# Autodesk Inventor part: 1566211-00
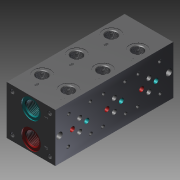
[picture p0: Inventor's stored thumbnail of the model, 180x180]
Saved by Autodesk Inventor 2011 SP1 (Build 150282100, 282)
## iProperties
Created: 2015-09
Part Number: 1566211-00
Catalog Web Link: www.cadenas.de
Description: P2A*L-Manifolds for ISO 4401-03 (CETOP 03) valves with side ports
Vendor: DUPLOMATIC
Document SubType Name: Modeling
Designer: PARTuser1
Manufacturer: DUPLOMATIC
Mass: 724.364 g
Surface Area: 890.578 cm^2
Volume: 724.364 cm^3
Density: 1 g/cm^3
Category: PARTsolutions
Company: DUPLOMATIC
Title: P2A3L/11
Author: Cadenas PARTsolutions
Comments: Manifolds for ISO 4401-03 (CETOP 03) valves with side ports
PSOL_IDENT_0: {$CADENAS_DATA\23d-libs\duplomatic\05_subplates_and_manifolds\52100\p2al.prj},162 {VTYP=3D},{NB=1566
PSOL_IDENT_1: 211-00},{LINA=P2A3L/11},{NN=P2A*L},{DATE=23.07.2015 05:38:35},{GEOMDATE=08.11.2012 00:00:00},{VERSIO
PSOL_IDENT_2: N=},{LINEID=10},{LINESUBID=-1},{WBVAR=VER}  {NB=1566211-00},{LINA=P2A3L/11},{KT=DUMMY},{CODE=1566211
PSOL_IDENT_3: -00},{TIPO=P2A},{VER=3},{PORT=L = Side ports},{SER=11}
NN: P2A*L
NT: Manifolds for ISO 4401-03 (CETOP 03) valves with side ports
NB: 1566211-00
NBSYN: $CODE.
LINA: P2A3L/11
OFFICIAL_STANDARD_NUMBERS: NO
TIPO: P2A
VER: 3 = 3 mounting positions
PORT: L = Side ports
SER: 11
SUPPLIER: DUPLOMATIC
ARTICLENO: 1566211-00
BOMINFO: P2A3L/11
CREATOR: CADENAS GmbH
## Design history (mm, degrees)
sketch "Sketch_1"
  geometry: L1 (-35, 170)-(-35, 0); L2 (-35, 0)-(35, 0); L3 (35, 0)-(35, 170); L4 (35, 170)-(-35, 170)
  constraints: 8 end point
extrude "Extrusion1" join sketch "Sketch_1" stored distance "d0" = 70; taper "d1" = 0 deg
sketch "Sketch_2"
  geometry: L1 (35, 6)-(-35, 6); L2 (-35, 6)-(-35, 10); L3 (-35, 10)-(-34.324, 9.323); L4 (-34.324, 9.323)-(-16.919, 9.323); L5 (-16.919, 9.323)-(-16.588, 8.75); L6 (-16.588, 8.75)-(25, 8.75); L7 (25, 8.75)-(25, 10.5); L8 (25, 10.5)-(35, 10.5); L9 (35, 10.5)-(35, 6); L10 (35, 6)-(-35, 6)
  constraints: 20 end point
revolve "Revolution1" sketch "Sketch_2" stored, may be unused: angle "d2" = 360 deg
thread "Thread1" dims "d3" = 12.3235, "d4" = 0
sketch "Sketch_3"
  geometry: L1 (35, 164)-(-35, 164); L2 (-35, 164)-(-35, 168); L3 (-35, 168)-(-34.324, 167.323); L4 (-34.324, 167.323)-(-16.919, 167.323); L5 (-16.919, 167.323)-(-16.588, 166.75); L6 (-16.588, 166.75)-(25, 166.75); L7 (25, 166.75)-(25, 168.5); L8 (25, 168.5)-(35, 168.5); L9 (35, 168.5)-(35, 164); L10 (35, 164)-(-35, 164)
  constraints: 20 end point
revolve "Revolution2" sketch "Sketch_3" stored, may be unused: angle "d5" = 360 deg
thread "Thread2" dims "d6" = 12.3235, "d7" = 0
sketch "Sketch4"
  geometry: 1 further point
hole "Hole1" sketch "Sketch4" at (14.75, 19.5) diameter "d8" = 4.134; stored, may be unused: countersink angle "d12" = 90 deg, drill point angle "d14" = 120 deg; dims "d9" = 9, "d10" = 5, "d11" = 2, "d13" = 10.80662
pattern_linear "Rectangular Pattern1" dims "d17" = 50, "d20" = 40.50694
sketch "Sketch5"
  geometry: 1 further point
hole "Hole2" sketch "Sketch5" at (14.75, 50.5) diameter "d21" = 4.134; stored, may be unused: countersink angle "d25" = 90 deg, drill point angle "d27" = 120 deg; dims "d22" = 9, "d23" = 5, "d24" = 2, "d26" = 10.80662
pattern_linear "Rectangular Pattern2" dims "d30" = 40.50694
sketch "Sketch6"
  geometry: 1 further point
hole "Hole3" sketch "Sketch6" at (36.25, 24.6) diameter "d34" = 7; stored, may be unused: countersink angle "d38" = 90 deg, drill point angle "d40" = 120 deg; dims "d35" = 6, "d36" = 4, "d37" = 2, "d39" = 15.97927
pattern_linear "Rectangular Pattern3" dims "d43" = 50, "d46" = 0
sketch "Sketch7"
  geometry: 1 further point
hole "Hole4" sketch "Sketch7" at (36.25, 45.4) diameter "d47" = 7; stored, may be unused: countersink angle "d51" = 90 deg, drill point angle "d53" = 120 deg; dims "d48" = 6, "d49" = 4, "d50" = 2, "d52" = 15.97927
pattern_linear "Rectangular Pattern4" dims "d56" = 50, "d59" = 0
sketch "Sketch8"
  geometry: 1 further point
hole "Hole5" sketch "Sketch8" at (27.45, 35) diameter "d60" = 7; stored, may be unused: countersink angle "d64" = 90 deg, drill point angle "d66" = 120 deg; dims "d61" = 6, "d62" = 4, "d63" = 2, "d65" = 15.97927
pattern_linear "Rectangular Pattern5" dims "d69" = 50, "d72" = 0
sketch "Sketch9"
  geometry: 1 further point
hole "Hole6" sketch "Sketch9" at (44.95, 35) diameter "d73" = 7; stored, may be unused: countersink angle "d77" = 90 deg, drill point angle "d79" = 120 deg; dims "d74" = 6, "d75" = 4, "d76" = 2, "d78" = 15.97927
pattern_linear "Rectangular Pattern6" dims "d82" = 50, "d85" = 0
sketch "Sketch_14"
  geometry: L1 (-19, -35)-(-19, -11.684); L2 (-19, -11.684)-(-11.525, -16); L3 (-11.525, -16)-(-11.525, -33.644); L4 (-11.525, -33.644)-(-10.669, -34.5); L5 (-10.669, -34.5)-(-7, -34.5); L6 (-7, -34.5)-(-7, -35); L7 (-7, -35)-(-19, -35); L8 (-19, -35)-(-19, -11.684)
  constraints: 16 end point
revolve "Revolution3" sketch "Sketch_14" stored, may be unused: angle "d86" = 360 deg
thread "Thread3" dims "d87" = 12.144, "d88" = 0
pattern_linear "Rectangular Pattern7" dims "d91" = 38
sketch "Sketch11"
  geometry: 1 further point
hole "Hole7" sketch "Sketch11" at (8, -8) diameter "d95" = 4.917; stored, may be unused: countersink angle "d99" = 90 deg, drill point angle "d101" = 120 deg; dims "d96" = 12, "d97" = 6, "d98" = 2, "d100" = 16.58058
pattern_linear "Rectangular Pattern8" dims "d104" = 54, "d107" = 54
sketch "Sketch_18"
  geometry: L1 (0, 19)-(85, 19); L2 (85, 19)-(85, 11.5); L3 (85, 11.5)-(24.448, 11.5); L4 (24.448, 11.5)-(23.4, 9.684); L5 (23.4, 9.684)-(2.562, 9.684); L6 (2.562, 9.684)-(1.4, 8.523); L7 (1.4, 8.523)-(1.4, 5); L8 (1.4, 5)-(0, 5); L9 (0, 5)-(0, 19); L10 (0, 19)-(85, 19)
  constraints: 20 end point
revolve "Revolution4" sketch "Sketch_18" stored, may be unused: angle "d108" = 360 deg
thread "Thread4" dims "d109" = 14.838, "d110" = 0
sketch "Sketch_19"
  geometry: L1 (0, -19)-(85, -19); L2 (85, -19)-(85, -26.5); L3 (85, -26.5)-(24.448, -26.5); L4 (24.448, -26.5)-(23.4, -28.316); L5 (23.4, -28.316)-(2.562, -28.316); L6 (2.562, -28.316)-(1.4, -29.477); L7 (1.4, -29.477)-(1.4, -33); L8 (1.4, -33)-(0, -33); L9 (0, -33)-(0, -19); L10 (0, -19)-(85, -19)
  constraints: 20 end point
revolve "Revolution5" sketch "Sketch_19" stored, may be unused: angle "d111" = 360 deg
thread "Thread5" dims "d112" = 14.838, "d113" = 0
sketch "Sketch_20"
  geometry: L1 (85, 19)-(170, 19); L2 (170, 19)-(170, 4); L3 (170, 4)-(169.5, 4); L4 (169.5, 4)-(169.5, 8.523); L5 (169.5, 8.523)-(168.338, 9.684); L6 (168.338, 9.684)-(147.5, 9.684); L7 (147.5, 9.684)-(146.452, 11.5); L8 (146.452, 11.5)-(85, 11.5); L9 (85, 11.5)-(85, 19); L10 (85, 19)-(170, 19)
  constraints: 20 end point
revolve "Revolution6" sketch "Sketch_20" stored, may be unused: angle "d114" = 360 deg
thread "Thread6" dims "d115" = 14.838, "d116" = 0
sketch "Sketch_21"
  geometry: L1 (85, -19)-(170, -19); L2 (170, -19)-(170, -34); L3 (170, -34)-(169.5, -34); L4 (169.5, -34)-(169.5, -29.477); L5 (169.5, -29.477)-(168.338, -28.316); L6 (168.338, -28.316)-(147.5, -28.316); L7 (147.5, -28.316)-(146.452, -26.5); L8 (146.452, -26.5)-(85, -26.5); L9 (85, -26.5)-(85, -19); L10 (85, -19)-(170, -19)
  constraints: 20 end point
revolve "Revolution7" sketch "Sketch_21" stored, may be unused: angle "d117" = 360 deg
thread "Thread7" dims "d118" = 14.838, "d119" = 0
sketch "Sketch_22"
  geometry: L1 (-35, 47)-(-35, 25); L2 (-35, 25)-(35, 25); L3 (35, 25)-(35, 47); L4 (35, 47)-(-35, 47)
  constraints: 8 end point
extrude "Extrusion2" cut sketch "Sketch_22" distance "d120" = 0.5; taper "d121" = 0 deg
sketch "Sketch_23"
  geometry: L1 (-35, 47)-(-35, 25); L2 (-35, 25)-(35, 25); L3 (35, 25)-(35, 47); L4 (35, 47)-(-35, 47)
  constraints: 8 end point
extrude "Extrusion3" join sketch "Sketch_23" distance "d122" = 0.5; taper "d123" = 0 deg
sketch "Sketch_24"
  geometry: L1 (-16.745, 30.5)-(13.079, 30.5); L2 (13.079, 39.5)-(-16.745, 39.5); L3 (8.002, 35.622)-(9.027, 35.622); L4 (9.027, 35.622)-(9.027, 37.486); L5 (9.027, 37.486)-(8.569, 37.486); L6 (8.569, 37.486)-(8.569, 35.997); L7 (8.569, 35.997)-(7.979, 35.997); L8 (7.994, 37.751)-(9.027, 37.752); L9 (9.027, 37.752)-(9.027, 38.127); L10 (9.027, 38.127)-(8.021, 38.127); L11 (4.708, 31.873)-(5.302, 31.873); L12 (6.361, 32.917)-(6.361, 34.378); L13 (6.361, 34.378)-(5.903, 34.378); L14 (5.903, 34.378)-(5.903, 32.943); L15 (5.234, 32.249)-(4.708, 32.249); L16 (4.708, 32.249)-(4.708, 31.873); L17 (6.41, 36.628)-(6.41, 38.127); L18 (6.41, 38.127)-(5.951, 38.127); L19 (5.951, 38.127)-(5.951, 36.632); L20 (5.951, 36.632)-(5.945, 36.459); L21 (4.716, 36.47)-(4.712, 36.651); L22 (4.712, 36.651)-(4.712, 38.127); L23 (4.712, 38.127)-(4.254, 38.127); L24 (4.254, 38.127)-(4.254, 36.662); L25 (2.579, 31.873)-(3.345, 31.873); L26 (3.371, 34.378)-(2.579, 34.378); L27 (2.579, 34.378)-(2.579, 34.003); L28 (2.579, 34.003)-(3.292, 34.003); L29 (4.036, 33.315)-(2.579, 33.315); L30 (2.579, 33.315)-(2.579, 32.94); L31 (2.579, 32.94)-(4.036, 32.94); L32 (3.292, 32.249)-(2.579, 32.249); L33 (2.579, 32.249)-(2.579, 31.873); L34 (2.567, 36.516)-(3.3, 36.516); L35 (3.3, 36.516)-(3.3, 35.622); L36 (3.3, 35.622)-(3.758, 35.622); L37 (3.758, 35.622)-(3.758, 37.486); L38 (3.758, 37.486)-(3.3, 37.486); L39 (3.3, 37.486)-(3.3, 36.891); L40 (3.3, 36.891)-(2.612, 36.891); L41 (2.616, 37.751)-(3.758, 37.752); L42 (3.758, 37.752)-(3.758, 38.127); L43 (3.758, 38.127)-(2.59, 38.127); L44 (-0.321, 35.622)-(0.272, 35.622); L45 (1.332, 36.666)-(1.332, 38.127); L46 (1.332, 38.127)-(0.873, 38.127); L47 (0.873, 38.127)-(0.873, 36.692); L48 (0.206, 35.997)-(-0.321, 35.997); L49 (-0.321, 35.997)-(-0.321, 35.622); L50 (-1.575, 31.873)-(-0.55, 31.873); L51 (-0.55, 31.873)-(-0.55, 33.734); L52 (-0.55, 33.734)-(-1.008, 33.734); L53 (-1.008, 33.734)-(-1.008, 32.249); L54 (-1.008, 32.249)-(-1.598, 32.249); L55 (-1.583, 34.003)-(-0.55, 34.003); L56 (-0.55, 34.003)-(-0.55, 34.378); L57 (-0.55, 34.378)-(-1.557, 34.378); L58 (-3.656, 31.873)-(-3.198, 31.873); L59 (-3.198, 31.873)-(-3.198, 33.734); L60 (-3.198, 33.734)-(-3.656, 33.734); L61 (-3.656, 33.734)-(-3.656, 31.873); L62 (-3.656, 33.998)-(-3.198, 33.998); L63 (-3.198, 33.998)-(-3.198, 34.378); L64 (-3.198, 34.378)-(-3.656, 34.378)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; A1 r 4.5 centre (-16.745, 35) between (-16.745, 39.5) and (-16.745, 30.5); A2 r 5.4 centre (16.064, 35) between (13.079, 39.5) and (13.079, 30.5); A3 r 1.744 centre (8.513, 36.864) between (6.77, 36.921) and (6.989, 36.018); A4 r 0.637 centre (7.554, 36.312) between (6.989, 36.018) and (7.198, 35.783); A5 r 0.992 centre (7.726, 36.623) between (7.198, 35.783) and (7.641, 35.635); A6 r 4.787 centre (7.991, 40.409) between (7.641, 35.635) and (8.002, 35.622); A7 r 1.499 centre (8.013, 37.496) between (7.725, 36.025) and (7.979, 35.997); A8 r 0.575 centre (7.871, 36.581) between (7.427, 36.215) and (7.725, 36.025); A9 r 1.675 centre (8.945, 36.923) between (7.27, 36.903) and (7.427, 36.215); A10 r 1.373 centre (8.643, 36.858) between (7.476, 37.582) and (7.27, 36.903); A11 r 0.629 centre (7.901, 37.119) between (7.814, 37.741) and (7.476, 37.582); A12 r 1.546 centre (7.989, 36.206) between (7.994, 37.751) and (7.814, 37.741); A13 r 5.147 centre (8.198, 32.983) between (8.021, 38.127) and (7.513, 38.084); A14 r 0.682 centre (7.595, 37.408) between (7.513, 38.084) and (7.052, 37.819); A15 r 1.728 centre (8.497, 36.873) between (7.052, 37.819) and (6.77, 36.921); A16 r 1.969 centre (8.692, 33.147) between (6.821, 33.762) and (6.889, 32.355); A17 r 0.569 centre (7.417, 32.569) between (6.889, 32.355) and (7.122, 32.082); A18 r 1.583 centre (7.952, 33.43) between (7.122, 32.082) and (8.669, 32.019); A19 r 0.732 centre (8.333, 32.669) between (8.669, 32.019) and (8.937, 32.256); A20 r 1.17 centre (7.951, 32.887) between (8.937, 32.256) and (9.056, 32.5); A21 r 1.802 centre (7.365, 33.122) between (9.056, 32.5) and (8.998, 33.883); A22 r 0.934 centre (8.182, 33.428) between (8.998, 33.883) and (8.615, 34.256); A23 r 1.922 centre (7.873, 32.482) between (8.615, 34.256) and (7.916, 34.405); A24 r 1.411 centre (7.879, 32.994) between (7.916, 34.405) and (7.199, 34.23); A25 r 0.737 centre (7.551, 33.583) between (7.199, 34.23) and (6.935, 33.988); A26 r 0.652 centre (7.449, 33.587) between (6.935, 33.988) and (6.821, 33.762); A27 r 2.315 centre (5.323, 34.188) between (5.302, 31.873) and (5.824, 31.928); A28 r 0.981 centre (5.487, 32.849) between (5.824, 31.928) and (6.132, 32.11); A29 r 0.56 centre (5.756, 32.525) between (6.132, 32.11) and (6.297, 32.381); A30 r 2.044 centre (4.316, 32.887) between (6.297, 32.381) and (6.361, 32.917); A31 r 2.029 centre (3.873, 32.93) between (5.866, 32.549) and (5.903, 32.943); A32 r 0.386 centre (5.493, 32.647) between (5.782, 32.391) and (5.866, 32.549); A33 r 0.325 centre (5.542, 32.61) between (5.592, 32.289) and (5.782, 32.391); A34 r 1.963 centre (5.194, 34.211) between (5.234, 32.249) and (5.592, 32.289); A35 r 2.208 centre (6.461, 36.603) between (4.254, 36.662) and (4.278, 36.273); A36 r 0.593 centre (4.867, 36.347) between (4.278, 36.273) and (4.502, 35.879); A37 r 1.48 centre (5.378, 37.071) between (4.502, 35.879) and (5.362, 35.592); A38 r 1.307 centre (5.365, 36.899) between (5.362, 35.592) and (6.226, 35.915); A39 r 0.791 centre (5.604, 36.405) between (6.226, 35.915) and (6.384, 36.269); A40 r 2.632 centre (3.777, 36.636) between (6.384, 36.269) and (6.41, 36.628); A41 r 0.587 centre (5.359, 36.477) between (5.912, 36.282) and (5.945, 36.459); A42 r 0.658 centre (5.307, 36.541) between (5.82, 36.129) and (5.912, 36.282); A43 r 0.763 centre (5.335, 36.718) between (4.847, 36.133) and (5.82, 36.129); A44 r 0.302 centre (5.025, 36.376) between (4.735, 36.292) and (4.847, 36.133); A45 r 1.24 centre (5.955, 36.515) between (4.716, 36.47) and (4.735, 36.292); A46 r 2.294 centre (3.355, 34.167) between (3.345, 31.873) and (3.81, 31.919); A47 r 0.788 centre (3.663, 32.693) between (3.81, 31.919) and (4.269, 32.189); A48 r 1.684 centre (2.868, 33.122) between (4.269, 32.189) and (4.356, 33.91); A49 r 0.742 centre (3.697, 33.569) between (4.356, 33.91) and (4.119, 34.179); A50 r 0.903 centre (3.572, 33.46) between (4.119, 34.179) and (3.73, 34.349); A51 r 2.103 centre (3.383, 32.275) between (3.73, 34.349) and (3.371, 34.378); A52 r 0.838 centre (3.323, 33.165) between (3.782, 33.866) and (3.292, 34.003); A53 r 0.538 centre (3.478, 33.423) between (3.912, 33.74) and (3.782, 33.866); A54 r 0.891 centre (3.146, 33.286) between (4.036, 33.315) and (3.912, 33.74); A55 r 0.85 centre (3.186, 32.933) between (3.928, 32.518) and (4.036, 32.94); A56 r 0.629 centre (3.418, 32.886) between (3.648, 32.301) and (3.928, 32.518); A57 r 1.061 centre (3.319, 33.309) between (3.292, 32.249) and (3.648, 32.301); A58 r 0.88 centre (2.534, 37.312) between (1.655, 37.327) and (1.933, 36.67); A59 r 0.543 centre (2.286, 37.081) between (1.933, 36.67) and (2.208, 36.544); A60 r 2.389 centre (2.577, 38.904) between (2.208, 36.544) and (2.567, 36.516); A61 r 1.069 centre (2.614, 37.96) between (2.427, 36.908) and (2.612, 36.891); A62 r 0.317 centre (2.48, 37.22) between (2.267, 36.985) and (2.427, 36.908); A63 r 0.515 centre (2.663, 37.314) between (2.308, 37.688) and (2.267, 36.985); A64 r 0.295 centre (2.478, 37.446) between (2.436, 37.738) and (2.308, 37.688)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
  constraints: 322 end point, 278 point on circle, 139 centre point
extrude "Extrusion4" cut sketch "Sketch_24" distance "d124" = 0.5; taper "d125" = 0 deg
sketch "Sketch_25"
  geometry: A1 r 2.032 centre (9.254, 33.122) between (7.273, 33.575) and (7.271, 32.681); A2 r 0.604 centre (7.861, 32.809) between (7.271, 32.681) and (7.446, 32.37); A3 r 0.922 centre (7.964, 33.133) between (7.446, 32.37) and (7.942, 32.211); A4 r 0.924 centre (7.914, 33.134) between (7.942, 32.211) and (8.443, 32.377); A5 r 0.667 centre (7.967, 32.845) between (8.443, 32.377) and (8.616, 32.689); A6 r 2.162 centre (6.503, 33.146) between (8.616, 32.689) and (8.649, 33.406); A7 r 0.872 centre (7.781, 33.329) between (8.649, 33.406) and (8.562, 33.717); A8 r 0.409 centre (8.188, 33.551) between (8.562, 33.717) and (8.454, 33.861); A9 r 0.834 centre (7.938, 33.206) between (8.454, 33.861) and (7.452, 33.884); A10 r 0.523 centre (7.789, 33.483) between (7.452, 33.884) and (7.273, 33.575)
  constraints: 20 point on circle, 10 centre point
extrude "Extrusion5" cut sketch "Sketch_25" distance "d126" = 0.5; taper "d127" = 0 deg
sketch "Sketch_26"
  geometry: A1 r 2.032 centre (2.373, 33.122) between (0.393, 33.575) and (0.39, 32.681); A2 r 0.604 centre (0.98, 32.809) between (0.39, 32.681) and (0.565, 32.37); A3 r 0.922 centre (1.083, 33.133) between (0.565, 32.37) and (1.061, 32.211); A4 r 0.924 centre (1.034, 33.134) between (1.061, 32.211) and (1.562, 32.377); A5 r 0.667 centre (1.086, 32.845) between (1.562, 32.377) and (1.735, 32.689); A6 r 2.162 centre (-0.378, 33.146) between (1.735, 32.689) and (1.769, 33.406); A7 r 0.872 centre (0.9, 33.329) between (1.769, 33.406) and (1.681, 33.717); A8 r 0.409 centre (1.307, 33.551) between (1.681, 33.717) and (1.573, 33.861); A9 r 0.834 centre (1.057, 33.206) between (1.573, 33.861) and (0.571, 33.884); A10 r 0.523 centre (0.908, 33.483) between (0.571, 33.884) and (0.393, 33.575)
  constraints: 20 point on circle, 10 centre point
extrude "Extrusion6" cut sketch "Sketch_26" distance "d128" = 0.5; taper "d129" = 0 deg
sketch "Sketch_27"
  geometry: A1 r 2.032 centre (-0.327, 36.871) between (-2.307, 37.324) and (-2.31, 36.43); A2 r 0.604 centre (-1.72, 36.557) between (-2.31, 36.43) and (-2.135, 36.119); A3 r 0.922 centre (-1.617, 36.882) between (-2.135, 36.119) and (-1.639, 35.96); A4 r 0.924 centre (-1.666, 36.883) between (-1.639, 35.96) and (-1.138, 36.126); A5 r 0.667 centre (-1.614, 36.594) between (-1.138, 36.126) and (-0.965, 36.438); A6 r 2.162 centre (-3.078, 36.895) between (-0.965, 36.438) and (-0.931, 37.155); A7 r 0.872 centre (-1.8, 37.078) between (-0.931, 37.155) and (-1.019, 37.466); A8 r 0.409 centre (-1.393, 37.3) between (-1.019, 37.466) and (-1.127, 37.61); A9 r 0.834 centre (-1.643, 36.955) between (-1.127, 37.61) and (-2.129, 37.632); A10 r 0.523 centre (-1.792, 37.232) between (-2.129, 37.632) and (-2.307, 37.324)
  constraints: 20 point on circle, 10 centre point
extrude "Extrusion7" cut sketch "Sketch_27" distance "d130" = 0.5; taper "d131" = 0 deg
sketch "Sketch_28"
  geometry: L1 (-8.34, 32.868)-(-7.502, 32.868); L2 (-7.502, 32.868)-(-7.927, 33.943); L3 (-7.927, 33.943)-(-8.34, 32.868)
  constraints: 6 end point
extrude "Extrusion8" cut sketch "Sketch_28" distance "d132" = 0.5; taper "d133" = 0 deg
sketch "Sketch_29"
  geometry: L1 (-17.613, 32.868)-(-16.775, 32.868); L2 (-16.775, 32.868)-(-17.2, 33.943); L3 (-17.2, 33.943)-(-17.613, 32.868)
  constraints: 6 end point
extrude "Extrusion9" cut sketch "Sketch_29" distance "d134" = 0.5; taper "d135" = 0 deg
sketch "Sketch_30"
  geometry: L1 (-8.046, 36.617)-(-7.209, 36.617); L2 (-7.209, 36.617)-(-7.633, 37.691); L3 (-7.633, 37.691)-(-8.046, 36.617)
  constraints: 6 end point
extrude "Extrusion10" cut sketch "Sketch_30" distance "d136" = 0.5; taper "d137" = 0 deg
sketch "Sketch_31"
  geometry: L1 (-35, 47)-(-35, 25); L2 (-35, 25)-(35, 25); L3 (35, 25)-(35, 47); L4 (35, 47)-(-35, 47); L5 (-16.745, 30.5)-(13.079, 30.5); L6 (13.079, 39.5)-(-16.745, 39.5); A1 r 4.5 centre (-16.745, 35) between (-16.745, 39.5) and (-16.745, 30.5); A2 r 5.4 centre (16.064, 35) between (13.079, 39.5) and (13.079, 30.5)
  constraints: 12 end point, 4 point on circle, 2 centre point
extrude "Extrusion11" cut sketch "Sketch_31" distance "d138" = 0.5; taper "d139" = 0 deg
sketch "Sketch_32"
  geometry: L1 (-35, 47)-(-35, 25); L2 (-35, 25)-(35, 25); L3 (35, 25)-(35, 47); L4 (35, 47)-(-35, 47); L5 (-16.745, 30.5)-(13.079, 30.5); L6 (13.079, 39.5)-(-16.745, 39.5); A1 r 4.5 centre (-16.745, 35) between (-16.745, 39.5) and (-16.745, 30.5); A2 r 5.4 centre (16.064, 35) between (13.079, 39.5) and (13.079, 30.5)
  constraints: 12 end point, 4 point on circle, 2 centre point
extrude "Extrusion12" join sketch "Sketch_32" distance "d140" = 0.5; taper "d141" = 0 deg
sketch "Sketch_33"
  geometry: L1 (16.8, 30.5)-(21.3, 30.5); L2 (21.3, 30.5)-(21.3, 36.882); L3 (21.3, 36.882)-(17.649, 36.882); L4 (17.649, 36.882)-(19.5, 32.3); L5 (19.5, 32.3)-(16.8, 32.3); L6 (16.8, 37.7)-(21.3, 37.7); L7 (21.3, 37.7)-(20.573, 39.5); L8 (20.573, 39.5)-(16.8, 39.5); A1 r 4.5 centre (16.8, 35) between (16.8, 39.5) and (16.8, 30.5); A2 r 2.7 centre (16.8, 35) between (16.8, 37.7) and (16.8, 32.3)
  constraints: 16 end point, 4 point on circle, 2 centre point
extrude "Extrusion13" cut sketch "Sketch_33" distance "d142" = 0.5; taper "d143" = 0 deg
sketch "Sketch_34"
  geometry: L1 (19, 18)-(19, 17.5); L2 (19, 17.5)-(24, 17.5); L3 (24, 17.5)-(24, 19); L4 (21, 19)-(21, 18); L5 (21, 18)-(19, 18); L6 (21.5, 19)-(21.5, 18); L7 (21.5, 18)-(23.5, 18); L8 (23.5, 18)-(23.5, 19); A1 r 1.5 centre (22.5, 19) between (24, 19) and (21, 19); A2 r 1 centre (22.5, 19) between (23.5, 19) and (21.5, 19)
  constraints: 16 end point, 4 point on circle, 2 centre point
extrude "Extrusion14" cut sketch "Sketch_34" distance "d144" = 1; taper "d145" = 0 deg
sketch "Sketch_35"
  geometry: L1 (19, -19.25)-(23.5, -19.25); L2 (23.5, -19.25)-(23.5, -20.5); L3 (23.5, -20.5)-(24, -20.5); L4 (24, -20.5)-(24, -17.5); L5 (24, -17.5)-(23.5, -17.5); L6 (23.5, -17.5)-(23.5, -18.75); L7 (23.5, -18.75)-(19, -18.75); L8 (19, -18.75)-(19, -19.25)
  constraints: 16 end point
extrude "Extrusion15" cut sketch "Sketch_35" distance "d146" = 1; taper "d147" = 0 deg
sketch "Sketch_36"
  geometry: L1 (25, 18.5)-(27, 18.5); L2 (27, 18.5)-(27, 17.5); L3 (30, 17.5)-(30, 19); L4 (30, 19)-(25, 19); L5 (25, 19)-(25, 18.5); L6 (29.5, 17.5)-(29.5, 18.5); L7 (29.5, 18.5)-(27.5, 18.5); L8 (27.5, 18.5)-(27.5, 17.5); A1 r 1.5 centre (28.5, 17.5) between (27, 17.5) and (30, 17.5); A2 r 1 centre (28.5, 17.5) between (27.5, 17.5) and (29.5, 17.5)
  constraints: 16 end point, 4 point on circle, 2 centre point
extrude "Extrusion16" cut sketch "Sketch_36" distance "d148" = 1; taper "d149" = 0 deg
sketch "Sketch_37"
  geometry: L1 (25, -19.25)-(29.5, -19.25); L2 (29.5, -19.25)-(29.5, -20.5); L3 (29.5, -20.5)-(30, -20.5); L4 (30, -20.5)-(30, -17.5); L5 (30, -17.5)-(29.5, -17.5); L6 (29.5, -17.5)-(29.5, -18.75); L7 (29.5, -18.75)-(25, -18.75); L8 (25, -18.75)-(25, -19.25)
  constraints: 16 end point
extrude "Extrusion17" cut sketch "Sketch_37" distance "d150" = 1; taper "d151" = 0 deg
sketch "Sketch_38"
  geometry: L1 (-11.5, 21)-(-11.5, 16); L2 (-11.5, 16)-(-9.875, 16); L3 (-9.875, 21)-(-11.5, 21); L4 (-11, 18.75)-(-9.875, 18.75); L5 (-9.875, 20.5)-(-11, 20.5); L6 (-11, 20.5)-(-11, 18.75); L7 (-11, 18.25)-(-11, 16.5); L8 (-11, 16.5)-(-9.875, 16.5); L9 (-9.875, 18.25)-(-11, 18.25); A1 r 1.375 centre (-9.875, 17.375) between (-9.875, 16) and (-9.084, 18.5); A2 r 1.375 centre (-9.875, 19.625) between (-9.084, 18.5) and (-9.875, 21); A3 r 0.875 centre (-9.875, 19.625) between (-9.875, 18.75) and (-9.875, 20.5); A4 r 0.875 centre (-9.875, 17.375) between (-9.875, 16.5) and (-9.875, 18.25)
  constraints: 18 end point, 8 point on circle, 4 centre point
extrude "Extrusion18" cut sketch "Sketch_38" distance "d152" = 1; taper "d153" = 0 deg
pattern_linear "Rectangular Pattern9" dims "d156" = 50, "d159" = 0
sketch "Sketch_40"
  geometry: L1 (25.8, 16)-(26.315, 16); L2 (26.315, 16)-(26.69, 17.5); L3 (26.69, 17.5)-(27.91, 17.5); L4 (27.91, 17.5)-(28.285, 16); L5 (28.285, 16)-(28.8, 16); L6 (28.8, 16)-(27.55, 21); L7 (27.55, 21)-(27.05, 21); L8 (27.05, 21)-(25.8, 16); L9 (26.815, 18)-(27.785, 18); L10 (27.785, 18)-(27.3, 19.938); L11 (27.3, 19.938)-(26.815, 18)
  constraints: 22 end point
extrude "Extrusion19" cut sketch "Sketch_40" distance "d160" = 0.1; taper "d161" = 0 deg
pattern_linear "Rectangular Pattern10" dims "d164" = 50, "d167" = 0
body "Solid1"
